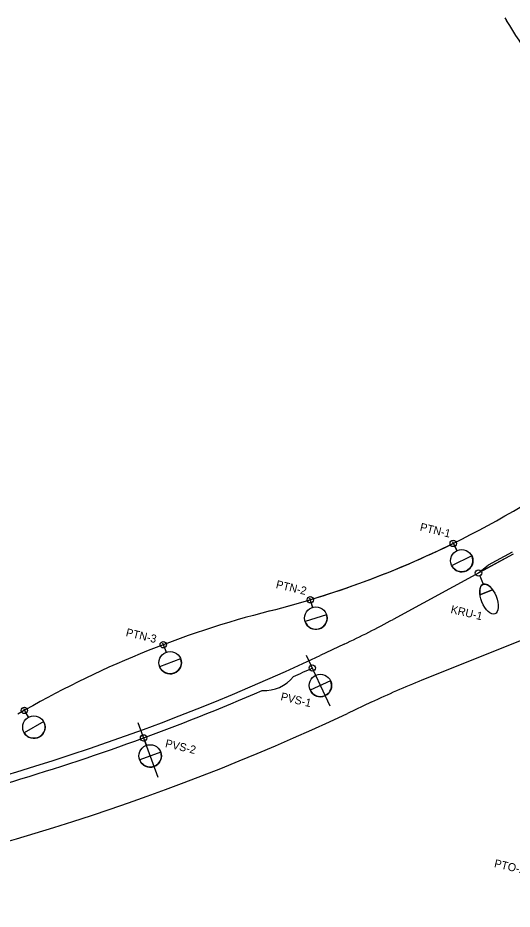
# Model space of a CAD drawing. Extents: x 0 to 511877, y 0 to 6211921.
# Drawn here: x 511654.3 to 511731.4, y 6211771.4 to 6211910.6 of the extents above; entities that cross this region are included whole.
import ezdxf

# ---------------------------------------------------------------- set-up
doc = ezdxf.new("R2010")
doc.units = 0
for name, color, linetype in [('Help', 7, 'Continuous'), ('TV_U_LYS_Ledn-', 7, 'Continuous'), ('TV_U_LYS_Mastenummer', 7, 'Continuous'), ('TV_U_LYS_Nyx330-Stamvej', 7, 'Continuous'), ('TV_U_LYS_Nyx330-Trafiksti', 7, 'Continuous'), ('TV_U_LYS_Nyx450-Rundkørsel', 7, 'Continuous')]:
    doc.layers.add(name, color=color, linetype=linetype)

msp = doc.modelspace()

# ---------------------------------------------------------------- linework, layer by layer
at = {"layer": 'Help'}
for p, q in [((511730.29, 6211910.56), (511730.56, 6211910.15)), ((511722.1, 6211828.81), (511722.73, 6211827.53)), ((511731.6, 6211826.85), (511712.88, 6211816.67)), ((511699.84, 6211820.04), (511700.25, 6211818.68)), ((511737.13, 6211815.1), (511717.35, 6211807.17)), ((511676.89, 6211813.02), (511677.39, 6211811.68)), ((511705.2, 6211812.78), (511701.5, 6211811.04)), ((511699.31, 6211811.1), (511702.98, 6211803.18)), ((511709.46, 6211803.73), (511705.76, 6211801.99)), ((511655.17, 6211802.74), (511655.87, 6211801.5)), ((511673.04, 6211800.58), (511676.17, 6211792.06))]:
    msp.add_line(p, q, dxfattribs=at)
for centre, radius, start, end in [((511606.44, 6211830), 147.75, 27.1845, 32.8498), ((511657.36, 6211960.49), 147.05, 284.2876, 303.3127), ((511731.4, 6211669.76), 152.95, 104.2876, 120.2652), ((511642.29, 6211946.47), 147.75, 295.1994, 298.5372), ((511554.61, 6212123.21), 345, 263.5186, 295.1994), ((511772.37, 6211670.04), 147.75, 111.861, 115.1994), ((511554.61, 6212123.21), 355, 263.5186, 295.1994)]:
    msp.add_arc(centre, radius, start, end, dxfattribs=at)
at = {"layer": 'TV_U_LYS_Ledn-'}
for p, q in [((511731.6, 6211826.85), (511726.2, 6211823.91)), ((511731.43, 6211827.16), (511727.69, 6211825.13)), ((511726.18, 6211823.91), (511727.69, 6211825.13))]:
    msp.add_line(p, q, dxfattribs=at)
for centre, radius, start, end in [((511657.36, 6211960.49), 147.05, 284.2876, 296.2104), ((511731.4, 6211669.76), 152.95, 104.2876, 120.2652), ((511554.61, 6212123.21), 346.25, 294.3396, 294.8768), ((511692.83, 6211811.28), 5.71, 266.1195, 321.6786), ((511554.61, 6212123.21), 346.25, 286.3745, 293.4585)]:
    msp.add_arc(centre, radius, start, end, dxfattribs=at)
at = {"layer": 'TV_U_LYS_Nyx330-Stamvej'}
for p, q in [((511700.46, 6211808.62), (511700.77, 6211807.94)), ((511703.1, 6211807.09), (511699.92, 6211805.61)), ((511703.1, 6211807.09), (511703.1, 6211807.09)), ((511674.1, 6211797.7), (511674.36, 6211796.99)), ((511676.61, 6211795.95), (511673.32, 6211794.74)), ((511676.61, 6211795.95), (511676.61, 6211795.95))]:
    msp.add_line(p, q, dxfattribs=at)
for centre, radius in [((511700.25, 6211809.08), 0.5), ((511701.51, 6211806.35), 1.75), ((511673.93, 6211798.16), 0.5), ((511674.96, 6211795.35), 1.75)]:
    msp.add_circle(centre, radius, dxfattribs=at)
for centre, start, end in [((511701.51, 6211806.35), 204.9179, 24.848), ((511674.96, 6211795.35), 200.2087, 20.1387)]:
    msp.add_arc(centre, 1.75, start, end, dxfattribs=at)
at = {"layer": 'TV_U_LYS_Nyx330-Trafiksti'}
for p, q in [((511722.46, 6211828.07), (511722.79, 6211827.4)), ((511725.14, 6211826.6), (511721.99, 6211825.05)), ((511725.14, 6211826.6), (511725.14, 6211826.6)), ((511700.08, 6211819.25), (511700.3, 6211818.54)), ((511702.48, 6211817.37), (511699.13, 6211816.35)), ((511702.48, 6211817.37), (511702.48, 6211817.37)), ((511677.18, 6211812.25), (511677.44, 6211811.54)), ((511679.71, 6211810.53), (511676.43, 6211809.28)), ((511679.71, 6211810.53), (511679.71, 6211810.53)), ((511655.58, 6211802.02), (511655.95, 6211801.37)), ((511658.34, 6211800.72), (511655.3, 6211798.98)), ((511658.34, 6211800.72), (511658.34, 6211800.72))]:
    msp.add_line(p, q, dxfattribs=at)
for centre, radius in [((511722.24, 6211828.52), 0.5), ((511723.56, 6211825.83), 1.75), ((511699.94, 6211819.73), 0.5), ((511700.81, 6211816.86), 1.75), ((511677, 6211812.71), 0.5), ((511678.07, 6211809.91), 1.75), ((511655.33, 6211802.46), 0.5), ((511656.82, 6211799.85), 1.75)]:
    msp.add_circle(centre, radius, dxfattribs=at)
for centre, start, end in [((511723.56, 6211825.83), 206.1795, 26.1095), ((511700.81, 6211816.86), 196.8431, 16.7731), ((511678.07, 6211809.91), 200.8647, 20.7947), ((511656.82, 6211799.85), 209.8536, 29.7837)]:
    msp.add_arc(centre, 1.75, start, end, dxfattribs=at)
at = {"layer": 'TV_U_LYS_Nyx450-Rundkørsel'}
for p, q in [((511726.37, 6211823.44), (511726.89, 6211822.14)), ((511728.39, 6211821.28), (511726.41, 6211820.48)), ((511726.41, 6211820.48), (511728.39, 6211821.28))]:
    msp.add_line(p, q, dxfattribs=at)
msp.add_circle((511726.18, 6211823.91), 0.5, dxfattribs=at)
msp.add_ellipse((511727.82, 6211819.83), major_axis=(0.93, -2.31), ratio=0.483744, dxfattribs=at)
msp.add_ellipse((511727.82, 6211819.83), major_axis=(0.93, -2.31), ratio=0.483744, start_param=2.042184, end_param=4.239581, dxfattribs=at)

# ---------------------------------------------------------------- texts
at = {"layer": 'TV_U_LYS_Mastenummer'}
for s, p in [('PTN-1', (511716.96, 6211830.53)), ('PTN-2', (511694.49, 6211821.58)), ('KRU-1', (511721.76, 6211817.68)), ('PTN-3', (511671.08, 6211814.08)), ('PVS-1', (511695.23, 6211804.07)), ('PVS-2', (511677.22, 6211796.76)), ('PTO-2', (511728.55, 6211778.03))]:
    msp.add_text(s, height=1.25, rotation=346.664, dxfattribs=at).set_placement(p)

doc.saveas('drawing.dxf')
